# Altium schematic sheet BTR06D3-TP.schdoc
size 127 x 101 mm
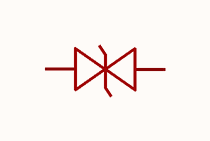
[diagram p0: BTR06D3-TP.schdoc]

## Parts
D?  btr06d3-tp  [D0603-BI]  (value not drawn)

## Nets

Not connected (* = marked no-connect by the designer): D? 1 2

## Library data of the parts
D? = btr06d3-tp: 反向截止电压(Vrwm):5.5V;钳位电压:9V;峰值脉冲电流(Ipp):5A@8/20ns;; Manufacturer: TECH PUBLIC(台舟); AddInBom: yes; ModelId: a387ce2936f842ebafc868b09fdf8ecc; ModelName: DO0603_L1.6-W0.8-H0.8-LS1.6; ModelTransform: 62.992,31.496,0,0,0,0,0,0,0; Reverse Stand-Off Voltage (Vrwm): 5.5V; Clamping Voltage: 9V; Reverse Leakage Current (Ir): 1nA; Number of Channels: 单路; level of protection: IEC 61000-4-5; Type: ESD; Junction Capacitance: 5pF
